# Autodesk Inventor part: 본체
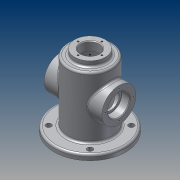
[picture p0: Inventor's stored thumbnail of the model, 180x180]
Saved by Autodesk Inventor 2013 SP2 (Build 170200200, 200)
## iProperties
Created: 2014-12
Part Number: 본체
Material: 알루미늄 6061
Document SubType Name: Modeling
Designer: user
Density: 2.71 g/cm^3
Mass: 479.567 g
Surface Area: 607.433 cm^2
Volume: 176.962 cm^3
Author: user
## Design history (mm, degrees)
sketch "스케치1"
  geometry: C1 r 32.5 at (0, 0); 1 further point
  constraints: 1 centre point, 1 coincident
  dimensions: "d0" = 65 diameter of C1
extrude "돌출1" new body sketch "스케치1" distance "d1" = 90; taper "d2" = 0 deg
sketch "스케치2"
  geometry: C1 r 22.5 at (0, 0); 1 further point
  constraints: 1 centre point, 1 coincident
  dimensions: "d3" = 45 diameter of C1
extrude "돌출2" join sketch "스케치2" distance "d4" = 8; taper "d5" = 0 deg
node "작업 평면2"
  node "작업 평면1"
sketch "스케치3"
  geometry: L1 (-32.5, -90)-(32.5, -90) reference; C1 r 25 at (0, -43); 1 further point
  constraints: 1 centre point
  dimensions: "d7" = 50 diameter of C1; "d8" = 47 distance from line of C1.centre L1
extrude "돌출3" join sketch "스케치3" stored distance "d9" = 10; taper "d10" = 0 deg
sketch "스케치4"
  geometry: C1 r 25 at (0, 0) reference; C2 r 16 at (0, 0); 1 further point
  constraints: 1 centre point, 1 coincident
  dimensions: "d11" = 32 diameter of C2
extrude "돌출4" cut sketch "스케치4" distance "d12" = 12; taper "d13" = 0 deg
sketch "스케치5"
  geometry: L1 (-47, 32.5)-(-47, -32.5) reference; C1 r 12.5 at (0, 0); 1 further point
  constraints: 1 centre point
  dimensions: "d14" = 25 diameter of C1; "d15" = 47 distance from line of C1.centre L1
sketch "스케치6"
  geometry: C1 r 27.5 at (0, 0); 1 further point
  constraints: 1 centre point, 1 coincident
  dimensions: "d16" = 55 diameter of C1
extrude "돌출5" cut sketch "스케치6" distance "d17" = 85; taper "d18" = 0 deg
extrude "돌출6" cut sketch "스케치5" stored distance "d19" = 85; taper "d20" = 0 deg
sketch "스케치7"
  geometry: C1 r 52.5 at (0, 0); 1 further point
  constraints: 1 centre point, 1 coincident
  dimensions: "d21" = 105 diameter of C1
extrude "돌출7" join sketch "스케치7" distance "d22" = 8; taper "d23" = 0 deg
sketch "스케치8"
  geometry: C1 r 27.5 at (0, 0); 1 further point
  constraints: 1 centre point, 1 coincident
  dimensions: "d24" = 55 diameter of C1
extrude "돌출8" cut sketch "스케치8" distance "d26" = 8; taper "d27" = 0 deg
sketch "스케치9"
  geometry: C1 r 25 at (0, 0) reference; 5 further points
hole "구멍1" sketch "스케치9" at (20.5, 0), (0, -20.5), (-20.5, 0), (0, 20.5) diameter "d29" = 2.459; stored, may be unused: countersink angle "d33" = 90 deg, drill point angle "d35" = 118 deg; dims "d30" = 6, "d31" = 4, "d32" = 2, "d34" = 8
sketch "스케치10"
  geometry: C1 r 13.5 at (0, 0); 1 further point
  constraints: 1 centre point, 1 coincident
  dimensions: "d36" = 27 diameter of C1
extrude "돌출9" cut sketch "스케치10" stored distance "d37" = 8; taper "d38" = 0 deg
sketch "스케치11"
  geometry: 5 further points
hole "구멍2" sketch "스케치11" at (0, 17.5), (17.5, 0), (0, -17.5), (-17.5, 0) diameter "d40" = 2.459; stored, may be unused: countersink angle "d44" = 90 deg, drill point angle "d46" = 118 deg; dims "d41" = 6, "d42" = 4, "d43" = 2, "d45" = 8
node "작업 평면3"
sketch "스케치12"
  geometry: 2 further points
  constraints: 1 other
  dimensions: "d47" = 9 vertical distance of point (0, 0) point (1.017, -9)
feature "엠보싱1" sketch "스케치12" dims "d13" = 0, "d48" = 1, "d49" = 0
sketch "스케치13"
  geometry: L1 (0, 0)-(100, 0); C1 r 4 at (30.406, 30.406); 1 further point
  constraints: 2 end point, 1 centre point, 1 coincident, 1 horizontal
  dimensions: "d53" = 8 diameter of C1
extrude "돌출10" cut sketch "스케치13" distance "d54" = 8; taper "d55" = 0 deg
fillet "모깎기1" dims "d59" = 3
chamfer "모따기1" distance "d60" = 1; stored, may be unused: second distance "d61" = 2, angle "d62" = 45 deg
fillet "모깎기2" dims "d63" = 0.3
fillet "모깎기3" dims "d64" = 3
sketch "스케치14"
  geometry: 1 further point
node "솔리드1"
mirror "대칭1"
pattern_circular "원형 패턴1" dims angle "d57" = 360 deg
